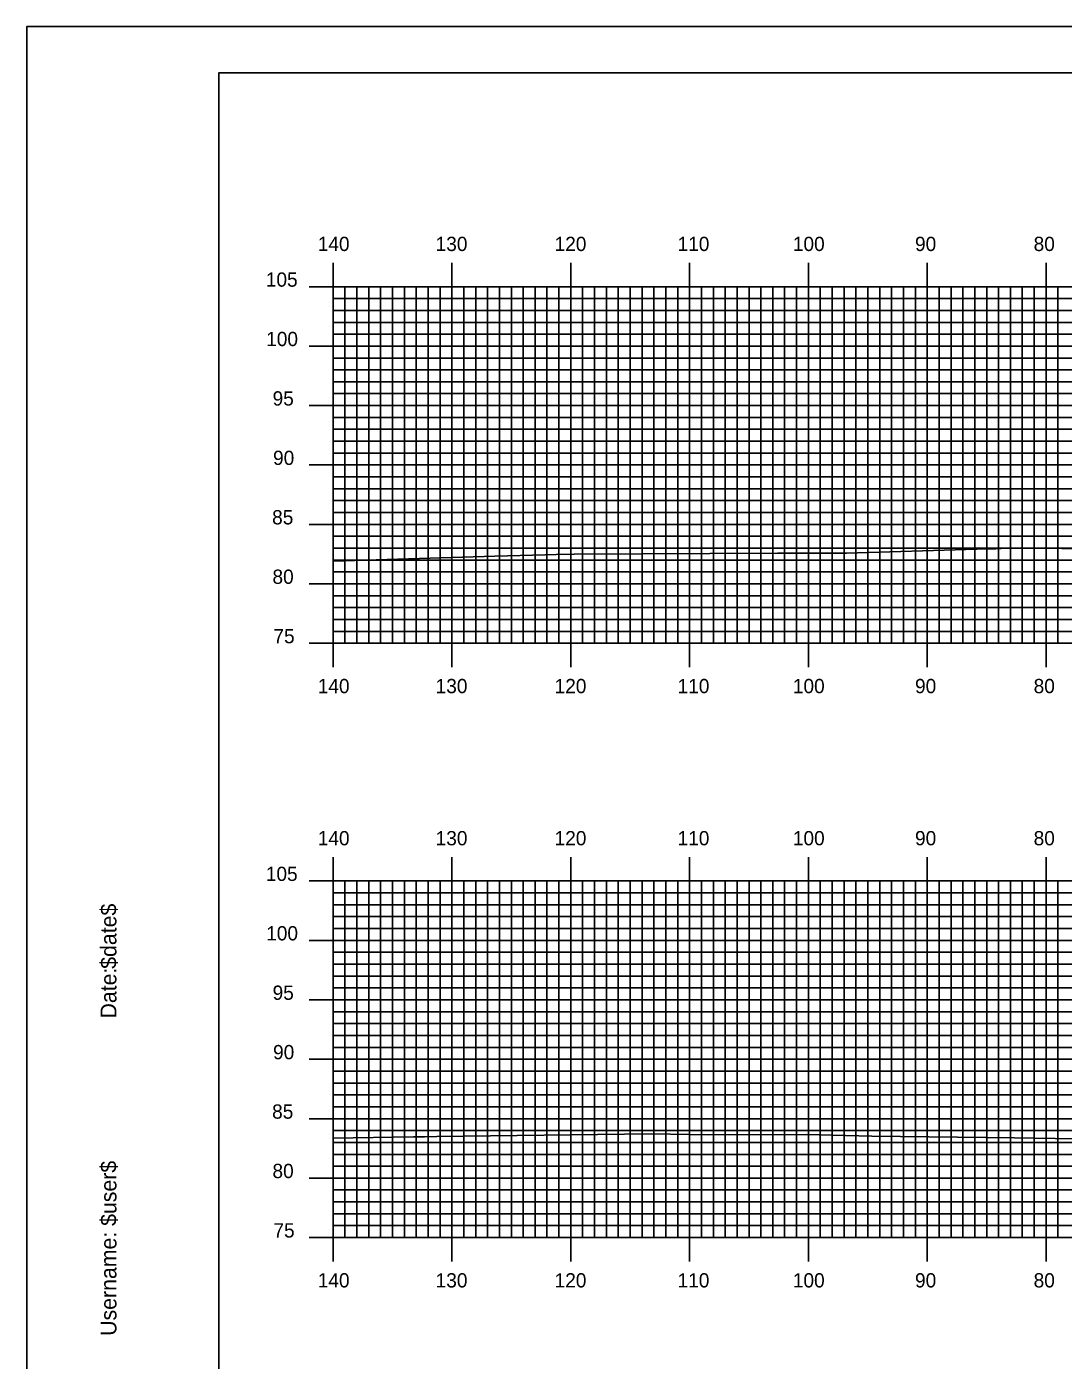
# Model space of a CAD drawing. Extents: x 1757856 to 1758199, y 442591 to 442811.
# Drawn here: x 1757855.8 to 1757943.1, y 442698.3 to 442810.5 of the extents above; entities that cross this region are included whole.
import ezdxf

# ---------------------------------------------------------------- set-up
doc = ezdxf.new("R2010")
doc.units = 0
for name, color, linetype in [('BORDER', 7, 'Continuous'), ('H_V ANNOTATION', 7, 'Continuous'), ('MAJOR', 7, 'Continuous'), ('MINOR', 7, 'Continuous'), ('PLOT BOUNDARY', 7, 'Continuous'), ('S_Roadway_Centerline', 7, 'Continuous')]:
    doc.layers.add(name, color=color, linetype=linetype)

msp = doc.modelspace()

# ---------------------------------------------------------------- linework, layer by layer
at = {"layer": 'BORDER'}
msp.add_lwpolyline([(1757872.02, 442596.67), (1758192.02, 442596.67), (1758192.02, 442806.67), (1757872.02, 442806.67)], close=True, dxfattribs=at)
at = {"layer": 'MAJOR'}
for p, q in [((1757881.62, 442790.67), (1757881.62, 442788.67)), ((1757891.62, 442790.67), (1757891.62, 442788.67)), ((1757901.62, 442790.67), (1757901.62, 442788.67)), ((1757911.62, 442790.67), (1757911.62, 442788.67)), ((1757921.62, 442790.67), (1757921.62, 442788.67)), ((1757931.62, 442790.67), (1757931.62, 442788.67)), ((1757941.62, 442790.67), (1757941.62, 442788.67)), ((1757879.62, 442788.67), (1757881.62, 442788.67)), ((1757881.62, 442788.67), (1758161.62, 442788.67)), ((1757881.62, 442758.67), (1757881.62, 442788.67)), ((1757881.62, 442758.67), (1757881.62, 442788.67)), ((1757881.62, 442788.67), (1758161.62, 442788.67)), ((1757891.62, 442758.67), (1757891.62, 442788.67)), ((1757901.62, 442758.67), (1757901.62, 442788.67)), ((1757911.62, 442758.67), (1757911.62, 442788.67)), ((1757921.62, 442758.67), (1757921.62, 442788.67)), ((1757931.62, 442758.67), (1757931.62, 442788.67)), ((1757941.62, 442758.67), (1757941.62, 442788.67)), ((1757879.62, 442783.67), (1757881.62, 442783.67)), ((1757881.62, 442783.67), (1758161.62, 442783.67)), ((1757879.62, 442778.67), (1757881.62, 442778.67)), ((1757881.62, 442778.67), (1758161.62, 442778.67)), ((1757879.62, 442773.67), (1757881.62, 442773.67)), ((1757881.62, 442773.67), (1758161.62, 442773.67)), ((1757879.62, 442768.67), (1757881.62, 442768.67)), ((1757881.62, 442768.67), (1758161.62, 442768.67)), ((1757879.62, 442763.67), (1757881.62, 442763.67)), ((1757881.62, 442763.67), (1758161.62, 442763.67)), ((1757879.62, 442758.67), (1757881.62, 442758.67)), ((1757881.62, 442758.67), (1758161.62, 442758.67)), ((1757881.62, 442758.67), (1758161.62, 442758.67)), ((1757881.62, 442756.66), (1757881.62, 442758.67)), ((1757891.62, 442756.66), (1757891.62, 442758.67)), ((1757901.62, 442756.66), (1757901.62, 442758.67)), ((1757911.62, 442756.66), (1757911.62, 442758.67)), ((1757921.62, 442756.66), (1757921.62, 442758.67)), ((1757931.62, 442756.66), (1757931.62, 442758.67)), ((1757941.62, 442756.66), (1757941.62, 442758.67)), ((1757881.62, 442740.67), (1757881.62, 442738.67)), ((1757891.62, 442740.67), (1757891.62, 442738.67)), ((1757901.62, 442740.67), (1757901.62, 442738.67)), ((1757911.62, 442740.67), (1757911.62, 442738.67)), ((1757921.62, 442740.67), (1757921.62, 442738.67)), ((1757931.62, 442740.67), (1757931.62, 442738.67)), ((1757941.62, 442740.67), (1757941.62, 442738.67)), ((1757879.62, 442738.67), (1757881.62, 442738.67)), ((1757881.62, 442738.67), (1758161.62, 442738.67)), ((1757881.62, 442708.67), (1757881.62, 442738.67)), ((1757881.62, 442708.67), (1757881.62, 442738.67)), ((1757881.62, 442738.67), (1758161.62, 442738.67)), ((1757891.62, 442708.67), (1757891.62, 442738.67)), ((1757901.62, 442708.67), (1757901.62, 442738.67)), ((1757911.62, 442708.67), (1757911.62, 442738.67)), ((1757921.62, 442708.67), (1757921.62, 442738.67)), ((1757931.62, 442708.67), (1757931.62, 442738.67)), ((1757941.62, 442708.67), (1757941.62, 442738.67)), ((1757879.62, 442733.67), (1757881.62, 442733.67)), ((1757881.62, 442733.67), (1758161.62, 442733.67)), ((1757879.62, 442728.67), (1757881.62, 442728.67)), ((1757881.62, 442728.67), (1758161.62, 442728.67)), ((1757879.62, 442723.67), (1757881.62, 442723.67)), ((1757881.62, 442723.67), (1758161.62, 442723.67)), ((1757879.62, 442718.67), (1757881.62, 442718.67)), ((1757881.62, 442718.67), (1758161.62, 442718.67)), ((1757879.62, 442713.67), (1757881.62, 442713.67)), ((1757881.62, 442713.67), (1758161.62, 442713.67)), ((1757879.62, 442708.67), (1757881.62, 442708.67)), ((1757881.62, 442708.67), (1758161.62, 442708.67)), ((1757881.62, 442708.67), (1758161.62, 442708.67)), ((1757881.62, 442706.66), (1757881.62, 442708.67)), ((1757891.62, 442706.66), (1757891.62, 442708.67)), ((1757901.62, 442706.66), (1757901.62, 442708.67)), ((1757911.62, 442706.66), (1757911.62, 442708.67)), ((1757921.62, 442706.66), (1757921.62, 442708.67)), ((1757931.62, 442706.66), (1757931.62, 442708.67)), ((1757941.62, 442706.66), (1757941.62, 442708.67))]:
    msp.add_line(p, q, dxfattribs=at)
at = {"layer": 'MINOR'}
for p, q in [((1757882.62, 442758.67), (1757882.62, 442788.67)), ((1757883.62, 442758.67), (1757883.62, 442788.67)), ((1757884.62, 442758.67), (1757884.62, 442788.67)), ((1757885.62, 442758.67), (1757885.62, 442788.67)), ((1757886.62, 442758.67), (1757886.62, 442788.67)), ((1757887.62, 442758.67), (1757887.62, 442788.67)), ((1757888.62, 442758.67), (1757888.62, 442788.67)), ((1757889.62, 442758.67), (1757889.62, 442788.67)), ((1757890.62, 442758.67), (1757890.62, 442788.67)), ((1757892.62, 442758.67), (1757892.62, 442788.67)), ((1757893.62, 442758.67), (1757893.62, 442788.67)), ((1757894.62, 442758.67), (1757894.62, 442788.67)), ((1757895.62, 442758.67), (1757895.62, 442788.67)), ((1757896.62, 442758.67), (1757896.62, 442788.67)), ((1757897.62, 442758.67), (1757897.62, 442788.67)), ((1757898.62, 442758.67), (1757898.62, 442788.67)), ((1757899.62, 442758.67), (1757899.62, 442788.67)), ((1757900.62, 442758.67), (1757900.62, 442788.67)), ((1757902.62, 442758.67), (1757902.62, 442788.67)), ((1757903.62, 442758.67), (1757903.62, 442788.67)), ((1757904.62, 442758.67), (1757904.62, 442788.67)), ((1757905.62, 442758.67), (1757905.62, 442788.67)), ((1757906.62, 442758.67), (1757906.62, 442788.67)), ((1757907.62, 442758.67), (1757907.62, 442788.67)), ((1757908.62, 442758.67), (1757908.62, 442788.67)), ((1757909.62, 442758.67), (1757909.62, 442788.67)), ((1757910.62, 442758.67), (1757910.62, 442788.67)), ((1757912.62, 442758.67), (1757912.62, 442788.67)), ((1757913.62, 442758.67), (1757913.62, 442788.67)), ((1757914.62, 442758.67), (1757914.62, 442788.67)), ((1757915.62, 442758.67), (1757915.62, 442788.67)), ((1757916.62, 442758.67), (1757916.62, 442788.67)), ((1757917.62, 442758.67), (1757917.62, 442788.67)), ((1757918.62, 442758.67), (1757918.62, 442788.67)), ((1757919.62, 442758.67), (1757919.62, 442788.67)), ((1757920.62, 442758.67), (1757920.62, 442788.67)), ((1757922.62, 442758.67), (1757922.62, 442788.67)), ((1757923.62, 442758.67), (1757923.62, 442788.67)), ((1757924.62, 442758.67), (1757924.62, 442788.67)), ((1757925.62, 442758.67), (1757925.62, 442788.67)), ((1757926.62, 442758.67), (1757926.62, 442788.67)), ((1757927.62, 442758.67), (1757927.62, 442788.67)), ((1757928.62, 442758.67), (1757928.62, 442788.67)), ((1757929.62, 442758.67), (1757929.62, 442788.67)), ((1757930.62, 442758.67), (1757930.62, 442788.67)), ((1757932.62, 442758.67), (1757932.62, 442788.67)), ((1757933.62, 442758.67), (1757933.62, 442788.67)), ((1757934.62, 442758.67), (1757934.62, 442788.67)), ((1757935.62, 442758.67), (1757935.62, 442788.67)), ((1757936.62, 442758.67), (1757936.62, 442788.67)), ((1757937.62, 442758.67), (1757937.62, 442788.67)), ((1757938.62, 442758.67), (1757938.62, 442788.67)), ((1757939.62, 442758.67), (1757939.62, 442788.67)), ((1757940.62, 442758.67), (1757940.62, 442788.67)), ((1757942.62, 442758.67), (1757942.62, 442788.67)), ((1757881.62, 442787.67), (1758161.62, 442787.67)), ((1757881.62, 442787.67), (1757883.63, 442787.67)), ((1757881.62, 442786.67), (1758161.62, 442786.67)), ((1757881.62, 442786.67), (1757883.63, 442786.67)), ((1757881.62, 442785.67), (1758161.62, 442785.67)), ((1757881.62, 442785.67), (1757883.63, 442785.67)), ((1757881.62, 442784.67), (1758161.62, 442784.67)), ((1757881.62, 442784.67), (1757883.63, 442784.67)), ((1757881.62, 442782.67), (1758161.62, 442782.67)), ((1757881.62, 442782.67), (1757883.63, 442782.67)), ((1757881.62, 442781.67), (1758161.62, 442781.67)), ((1757881.62, 442781.67), (1757883.63, 442781.67)), ((1757881.62, 442780.67), (1758161.62, 442780.67)), ((1757881.62, 442780.67), (1757883.63, 442780.67)), ((1757881.62, 442779.67), (1758161.62, 442779.67)), ((1757881.62, 442779.67), (1757883.63, 442779.67)), ((1757881.62, 442777.67), (1758161.62, 442777.67)), ((1757881.62, 442777.67), (1757883.63, 442777.67)), ((1757881.62, 442776.67), (1758161.62, 442776.67)), ((1757881.62, 442776.67), (1757883.63, 442776.67)), ((1757881.62, 442775.67), (1758161.62, 442775.67)), ((1757881.62, 442775.67), (1757883.63, 442775.67)), ((1757881.62, 442774.67), (1758161.62, 442774.67)), ((1757881.62, 442774.67), (1757883.63, 442774.67)), ((1757881.62, 442772.67), (1758161.62, 442772.67)), ((1757881.62, 442772.67), (1757883.63, 442772.67)), ((1757881.62, 442771.67), (1758161.62, 442771.67)), ((1757881.62, 442771.67), (1757883.63, 442771.67)), ((1757881.62, 442770.67), (1758161.62, 442770.67)), ((1757881.62, 442770.67), (1757883.63, 442770.67)), ((1757881.62, 442769.67), (1758161.62, 442769.67)), ((1757881.62, 442769.67), (1757883.63, 442769.67)), ((1757881.62, 442767.67), (1758161.62, 442767.67)), ((1757881.62, 442767.67), (1757883.63, 442767.67)), ((1757881.62, 442766.67), (1758161.62, 442766.67)), ((1757881.62, 442766.67), (1757883.63, 442766.67)), ((1757881.62, 442765.67), (1758161.62, 442765.67)), ((1757881.62, 442765.67), (1757883.63, 442765.67)), ((1757881.62, 442764.67), (1758161.62, 442764.67)), ((1757881.62, 442764.67), (1757883.63, 442764.67)), ((1757881.62, 442762.67), (1758161.62, 442762.67)), ((1757881.62, 442762.67), (1757883.63, 442762.67)), ((1757881.62, 442761.67), (1758161.62, 442761.67)), ((1757881.62, 442761.67), (1757883.63, 442761.67)), ((1757881.62, 442760.67), (1758161.62, 442760.67)), ((1757881.62, 442760.67), (1757883.63, 442760.67)), ((1757881.62, 442759.67), (1758161.62, 442759.67)), ((1757881.62, 442759.67), (1757883.63, 442759.67)), ((1757882.62, 442708.67), (1757882.62, 442738.67)), ((1757883.62, 442708.67), (1757883.62, 442738.67)), ((1757884.62, 442708.67), (1757884.62, 442738.67)), ((1757885.62, 442708.67), (1757885.62, 442738.67)), ((1757886.62, 442708.67), (1757886.62, 442738.67)), ((1757887.62, 442708.67), (1757887.62, 442738.67)), ((1757888.62, 442708.67), (1757888.62, 442738.67)), ((1757889.62, 442708.67), (1757889.62, 442738.67)), ((1757890.62, 442708.67), (1757890.62, 442738.67)), ((1757892.62, 442708.67), (1757892.62, 442738.67)), ((1757893.62, 442708.67), (1757893.62, 442738.67)), ((1757894.62, 442708.67), (1757894.62, 442738.67)), ((1757895.62, 442708.67), (1757895.62, 442738.67)), ((1757896.62, 442708.67), (1757896.62, 442738.67)), ((1757897.62, 442708.67), (1757897.62, 442738.67)), ((1757898.62, 442708.67), (1757898.62, 442738.67)), ((1757899.62, 442708.67), (1757899.62, 442738.67)), ((1757900.62, 442708.67), (1757900.62, 442738.67)), ((1757902.62, 442708.67), (1757902.62, 442738.67)), ((1757903.62, 442708.67), (1757903.62, 442738.67)), ((1757904.62, 442708.67), (1757904.62, 442738.67)), ((1757905.62, 442708.67), (1757905.62, 442738.67)), ((1757906.62, 442708.67), (1757906.62, 442738.67)), ((1757907.62, 442708.67), (1757907.62, 442738.67)), ((1757908.62, 442708.67), (1757908.62, 442738.67)), ((1757909.62, 442708.67), (1757909.62, 442738.67)), ((1757910.62, 442708.67), (1757910.62, 442738.67)), ((1757912.62, 442708.67), (1757912.62, 442738.67)), ((1757913.62, 442708.67), (1757913.62, 442738.67)), ((1757914.62, 442708.67), (1757914.62, 442738.67)), ((1757915.62, 442708.67), (1757915.62, 442738.67)), ((1757916.62, 442708.67), (1757916.62, 442738.67)), ((1757917.62, 442708.67), (1757917.62, 442738.67)), ((1757918.62, 442708.67), (1757918.62, 442738.67)), ((1757919.62, 442708.67), (1757919.62, 442738.67)), ((1757920.62, 442708.67), (1757920.62, 442738.67)), ((1757922.62, 442708.67), (1757922.62, 442738.67)), ((1757923.62, 442708.67), (1757923.62, 442738.67)), ((1757924.62, 442708.67), (1757924.62, 442738.67)), ((1757925.62, 442708.67), (1757925.62, 442738.67)), ((1757926.62, 442708.67), (1757926.62, 442738.67)), ((1757927.62, 442708.67), (1757927.62, 442738.67)), ((1757928.62, 442708.67), (1757928.62, 442738.67)), ((1757929.62, 442708.67), (1757929.62, 442738.67)), ((1757930.62, 442708.67), (1757930.62, 442738.67)), ((1757932.62, 442708.67), (1757932.62, 442738.67)), ((1757933.62, 442708.67), (1757933.62, 442738.67)), ((1757934.62, 442708.67), (1757934.62, 442738.67)), ((1757935.62, 442708.67), (1757935.62, 442738.67)), ((1757936.62, 442708.67), (1757936.62, 442738.67)), ((1757937.62, 442708.67), (1757937.62, 442738.67)), ((1757938.62, 442708.67), (1757938.62, 442738.67)), ((1757939.62, 442708.67), (1757939.62, 442738.67)), ((1757940.62, 442708.67), (1757940.62, 442738.67)), ((1757942.62, 442708.67), (1757942.62, 442738.67)), ((1757881.62, 442737.67), (1758161.62, 442737.67)), ((1757881.62, 442737.67), (1757883.63, 442737.67)), ((1757881.62, 442736.67), (1758161.62, 442736.67)), ((1757881.62, 442736.67), (1757883.63, 442736.67)), ((1757881.62, 442735.67), (1758161.62, 442735.67)), ((1757881.62, 442735.67), (1757883.63, 442735.67)), ((1757881.62, 442734.67), (1758161.62, 442734.67)), ((1757881.62, 442734.67), (1757883.63, 442734.67)), ((1757881.62, 442732.67), (1758161.62, 442732.67)), ((1757881.62, 442732.67), (1757883.63, 442732.67)), ((1757881.62, 442731.67), (1758161.62, 442731.67)), ((1757881.62, 442731.67), (1757883.63, 442731.67)), ((1757881.62, 442730.67), (1758161.62, 442730.67)), ((1757881.62, 442730.67), (1757883.63, 442730.67)), ((1757881.62, 442729.67), (1758161.62, 442729.67)), ((1757881.62, 442729.67), (1757883.63, 442729.67)), ((1757881.62, 442727.67), (1758161.62, 442727.67)), ((1757881.62, 442727.67), (1757883.63, 442727.67)), ((1757881.62, 442726.67), (1758161.62, 442726.67)), ((1757881.62, 442726.67), (1757883.63, 442726.67)), ((1757881.62, 442725.67), (1758161.62, 442725.67)), ((1757881.62, 442725.67), (1757883.63, 442725.67)), ((1757881.62, 442724.67), (1758161.62, 442724.67)), ((1757881.62, 442724.67), (1757883.63, 442724.67)), ((1757881.62, 442722.67), (1758161.62, 442722.67)), ((1757881.62, 442722.67), (1757883.63, 442722.67)), ((1757881.62, 442721.67), (1758161.62, 442721.67)), ((1757881.62, 442721.67), (1757883.63, 442721.67)), ((1757881.62, 442720.67), (1758161.62, 442720.67)), ((1757881.62, 442720.67), (1757883.63, 442720.67)), ((1757881.62, 442719.67), (1758161.62, 442719.67)), ((1757881.62, 442719.67), (1757883.63, 442719.67)), ((1757881.62, 442717.67), (1758161.62, 442717.67)), ((1757881.62, 442717.67), (1757883.63, 442717.67)), ((1757881.62, 442716.67), (1758161.62, 442716.67)), ((1757881.62, 442716.67), (1757883.63, 442716.67)), ((1757881.62, 442715.67), (1758161.62, 442715.67)), ((1757881.62, 442715.67), (1757883.63, 442715.67)), ((1757881.62, 442714.67), (1758161.62, 442714.67)), ((1757881.62, 442714.67), (1757883.63, 442714.67)), ((1757881.62, 442712.67), (1758161.62, 442712.67)), ((1757881.62, 442712.67), (1757883.63, 442712.67)), ((1757881.62, 442711.67), (1758161.62, 442711.67)), ((1757881.62, 442711.67), (1757883.63, 442711.67)), ((1757881.62, 442710.67), (1758161.62, 442710.67)), ((1757881.62, 442710.67), (1757883.63, 442710.67)), ((1757881.62, 442709.67), (1758161.62, 442709.67)), ((1757881.62, 442709.67), (1757883.63, 442709.67))]:
    msp.add_line(p, q, dxfattribs=at)
at = {"layer": 'PLOT BOUNDARY'}
msp.add_lwpolyline([(1757855.84, 442590.55), (1758195.84, 442590.55), (1758195.84, 442810.55), (1757855.84, 442810.55)], close=True, dxfattribs=at)
at = {"layer": 'S_Roadway_Centerline'}
for points in [[(1757881.62, 442765.58), (1757895.24, 442766), (1757899.48, 442766.12), (1757900.4, 442766.14), (1757901.92, 442766.16), (1757919.02, 442766.24), (1757924.82, 442766.24), (1757935.79, 442766.58), (1757937.38, 442766.62), (1757938.28, 442766.67), (1757942.94, 442766.64), (1757957.7, 442766.56)], [(1757881.62, 442717.03), (1757888.4, 442717.13), (1757889.31, 442717.14), (1757890.34, 442717.16), (1757908.38, 442717.4), (1757913.25, 442717.3), (1757921.42, 442717.33), (1757926.97, 442717.2), (1757938.97, 442717.05), (1757947.5, 442716.92)]]:
    msp.add_lwpolyline(points, dxfattribs=at)

# ---------------------------------------------------------------- texts
at = {"layer": 'BORDER'}
for s, p in [('$date$', (1757863.39, 442731.28)), ('$date$', (1757863.39, 442731.28)), ('Date:', (1757863.39, 442727.1)), ('Date:', (1757863.39, 442727.1)), ('$user$', (1757863.39, 442709.65)), ('$user$', (1757863.39, 442709.65)), ('Username:', (1757863.39, 442700.4)), ('Username:', (1757863.39, 442700.4))]:
    msp.add_text(s, height=1.339, rotation=90, dxfattribs=at).set_placement(p)
at = {"layer": 'H_V ANNOTATION'}
for s, p in [('140', (1757880.33, 442791.67)), ('130', (1757890.25, 442791.67)), ('120', (1757900.26, 442791.67)), ('110', (1757910.61, 442791.67)), ('100', (1757920.31, 442791.67)), ('90', (1757930.59, 442791.67)), ('80', (1757940.57, 442791.67)), ('105', (1757875.96, 442788.67)), ('100', (1757875.99, 442783.67)), ('95', (1757876.53, 442778.67)), ('90', (1757876.57, 442773.67)), ('85', (1757876.49, 442768.67)), ('80', (1757876.52, 442763.67)), ('75', (1757876.6, 442758.67)), ('140', (1757880.33, 442754.47)), ('130', (1757890.25, 442754.47)), ('120', (1757900.26, 442754.47)), ('110', (1757910.61, 442754.47)), ('100', (1757920.31, 442754.47)), ('90', (1757930.59, 442754.47)), ('80', (1757940.57, 442754.47)), ('140', (1757880.33, 442741.67)), ('130', (1757890.25, 442741.67)), ('120', (1757900.26, 442741.67)), ('110', (1757910.61, 442741.67)), ('100', (1757920.31, 442741.67)), ('90', (1757930.59, 442741.67)), ('80', (1757940.57, 442741.67)), ('105', (1757875.96, 442738.67)), ('100', (1757875.99, 442733.67)), ('95', (1757876.53, 442728.67)), ('90', (1757876.57, 442723.67)), ('85', (1757876.49, 442718.67)), ('80', (1757876.52, 442713.67)), ('75', (1757876.6, 442708.67)), ('140', (1757880.33, 442704.47)), ('130', (1757890.25, 442704.47)), ('120', (1757900.26, 442704.47)), ('110', (1757910.61, 442704.47)), ('100', (1757920.31, 442704.47)), ('90', (1757930.59, 442704.47)), ('80', (1757940.57, 442704.47))]:
    msp.add_text(s, height=1.2, dxfattribs=at).set_placement(p)
at = {"layer": 'MAJOR'}
for p in [(1757881.61, 442758.67), (1757881.61, 442708.67)]:
    msp.add_text('-', height=0.012, dxfattribs=at).set_placement(p)

doc.saveas('drawing.dxf')
